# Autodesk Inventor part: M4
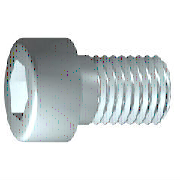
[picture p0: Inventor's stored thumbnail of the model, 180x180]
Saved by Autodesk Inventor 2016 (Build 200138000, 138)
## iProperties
IsCustomPart: 0
Created: 2016-04
Part Number: M4
Material: 강철, 연강
Description: 6각머리 태핑 나사
Document SubType Name: Modeling
Standard: KS B 1003
Designer: mdu
Standards Organization: KS
Language: ko-KR
Size Designation: M 4 x 10
Categories: <MemberInstance><Categories><Category DisplayName="조임쇠" InternalName="e4da775c-781d-43d5-af7c-5136215cf5a6" Mnemonic="FSTN"><Category DisplayName="볼트" InternalN
Density: 7.86 g/cm^3
Mass: 2.0371 g
Surface Area: 3.0572 cm^2
Volume: 0.259174 cm^3
Appearance: 금속 1800F 열
Author: mdu
Revision Number: 1
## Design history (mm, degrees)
sketch "스케치1"
  geometry: L1 (-1, 0)-(10, 0); L2 (10, 0)-(10, 2); L3 (10, 2)-(1.75, 2); L4 (1.75, 2)-(1.32, 2); L5 (1.32, 2)-(0, 2); L6 (0, 2)-(0, 3.5); L7 (0, 3.5)-(-4, 3.5); L8 (-4, 3.5)-(-4, 1.732); L9 (-4, 1.732)-(-2, 1.732); L10 (-2, 1.732)-(-1, 0); L11 (-6.8, 0)-(12.8, 0) reference; L12 (0, -0.7)-(0, 4.2) reference; L13 (1.75, 2)-(0, 2)
  constraints: 22 end point, 6 parallel, 2 collinear, 2 perpendicular, 1 horizontal, 1 point on line
  dimensions: "d1" = 8.25 distance from line of L3.end L2 (= GEL); "d2" = 0.42952 distance of L4.end L3.end (computed from GAL); "d3" = 4 distance between parallel lines of L8 L6 (= KOH); "d4" = 2 distance of L8.end L9.end (= INTI); "d5" = 60 deg angle of L10 L1; "d6" = 4 diameter of L3 L1 (= GD); "d7" = 4 diameter of L5 L1 (= BDM); "d8" = 3.4641 diameter of L9 L1 (= 1.1547 x SW); "d9" = 7 diameter of L7 L1 (= KOD); "d26" = 10 distance between parallel lines of L12 L2 (= NLG)
revolve "본체" sketch "스케치1" stored, may be unused: angle "d10" = 90 deg
sketch "스케치2"
  geometry: L1 (0, -4.9)-(0, 4.9) reference; L2 (-4.9, 0)-(4.9, 0) reference; L3 (1.732, 0)-(0.866, -1.5); L4 (0.866, -1.5)-(-0.866, -1.5); L5 (-0.866, -1.5)-(-1.732, 0); L6 (-1.732, 0)-(-0.866, 1.5); L7 (-0.866, 1.5)-(0.866, 1.5); L8 (0.866, 1.5)-(1.732, 0); 2 further points
  constraints: 12 end point, 1 coincident, 1 horizontal alignment, 1 point on line, 12 other
extrude "슬롯" join sketch "스케치2" stored distance "d11" = 10; taper "d12" = 0 deg
workplane "Work Plane1"
fillet "Fillet2" dims "d30" = 0.1 (= R)
body "Solid1"
fillet "모깎기1" dims "d17" = 0.4 (= RR)
feature "스레드" dims "d13" = 8.25 (= GEL), "d14" = 0
chamfer "모따기1" distance "d15" = 0.42941 (= -0.5 x SPD + 0.5 x GD); stored, may be unused: second distance "d16" = 0.42941 (= GUL), angle "d27" = 45 deg
other parameters: "GD" = 4 (= NND) [user parameter; used in 2 equation terms], "NLG" = 10 [user parameter; used in 1 equation term], "GEL" = 8.25 [user parameter; used in 2 equation terms], "KOD" = 7 [user parameter; used in 1 equation term], "KOH" = 4 [user parameter; used in 1 equation term], "INTI" = 2 [user parameter; used in 1 equation term], "GAL" = 0.42941 (= 0.61345 x PTC) [user parameter; used in 1 equation term], "GUL" = 0.42941 (= 0.61345 x PTC) [user parameter; used in 1 equation term], "BDM" = 4 (= NND) [user parameter; used in 1 equation term], "SW" = 3 [user parameter; used in 2 equation terms], "RR" = 0.4 [user parameter; used in 1 equation term], "SPD" = 3.14117 (= NND - 1.2269 x PTC) [user parameter; used in 1 equation term], "d19" = 0, "d28" = 0, "d29" = 0, "R" = 0.1 [user parameter; used in 1 equation term], "PHH" = 0.2 [user parameter], "GD1" = 3.14117 (= THREADDIA - 1.2269 x PTC) [user parameter], "THREADDIA" = 4 [user parameter; used in 1 equation term], "FAWI" = 45 deg [user parameter], "TPU" = 14.28571 (computed from PTC) [user parameter], "PTC" = 0.7 [user parameter; used in 5 equation terms], "NND" = 4 [user parameter; used in 3 equation terms], "TOA" = 30 deg [user parameter], "E0" = 3.465 (= 1.155 x SW) [user parameter]
